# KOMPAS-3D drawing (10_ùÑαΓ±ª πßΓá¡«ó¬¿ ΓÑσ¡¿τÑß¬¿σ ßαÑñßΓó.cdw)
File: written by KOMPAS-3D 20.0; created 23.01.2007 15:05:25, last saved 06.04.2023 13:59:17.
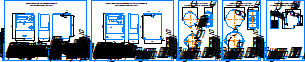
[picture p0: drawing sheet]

Sheets 1-2: A3, landscape
Sheets 3-5: A4, portrait

Document properties: Автор: Семёнов; Организация: СиТ; Разработал: Антошин; Проверил: Тарасов; Утвердил: Шмончев; Н. контр.: Силаков; Форматы листов документа: 3xA4, 2xA3; Полное имя файла: \\s-tech\depts\Отдел_ПКО\Проекты\Типовые проекты МКД 2023\!Типовой проект\1_Типовой проект МКД_RS-485\10_Чертёж установки технических средств.cdw

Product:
- Part/product: (unnamed)
  - Component: \\Helios\отдел_пко\Общая папка Компас\_Addons\Signatures\Signatures.lfr|Тарасов  | Полное имя файла: C:\Users\MAntoshin\AppData\Local\Temp\qlkzkl.frw; source file: C:\Program Files\ASCON\KOMPAS-3D V13\Libs\_Addons\Signatures\Signatures.lfr
  - Component: \\Helios\отдел_пко\Общая папка Компас\_Addons\Signatures\Signatures.lfr|Силаков  | Полное имя файла: C:\Users\MAntoshin\AppData\Local\Temp\eiczbt.frw; source file: C:\Program Files\ASCON\KOMPAS-3D V13\Libs\_Addons\Signatures\Signatures.lfr
  - Component: \\Helios\отдел_пко\Общая папка Компас\_Addons\Signatures\Signatures.lfr|Шмончев  | Полное имя файла: C:\Users\MAntoshin\AppData\Local\Temp\hsklda.frw; source file: C:\Program Files\ASCON\KOMPAS-3D V13\Libs\_Addons\Signatures\Signatures.lfr

Title block, sheet 1: designation: ВЛСТ 1277.01.000 СА; sheet number: 1; Количество листов документа: 30; organisation: АО ГК "Системы и Технологии"; Форматы листов документа: A3; stored path: \\Helios\departments\Отдел_ПКО\Проекты\Бийский Олеумный Завод\Проект\2_Рабочая документация\1_ГПП-2\СА_001_01_Чертёж установки технических средств.cdw; cell 302: Система учета электроэнергии (с организацией удаленного сбора данных) / потребителей; cell 303: Типовой проект АСКУЭ многоквартирного / дома с использованием проводного / канала связи RS-485; cell 304: Чертеж установки / технических средств; cell 320: Р
Title block, sheet 2: sheet number: 2; sheet number: 7; Форматы листов документа: A4; stored path: \\s-tech\depts\Отдел_ПКО\Проекты\Типовые проекты МКД 2023\!Типовой проект\1_Типовой проект МКД_RS-485\_Чертёж установки технических средств.cdw
Title block, sheet 3: sheet number: 3
Title block, sheet 4: sheet number: 4; stored path: \\Helios\отдел_пко\Проекты\МРСК Северо-Запада Псковэнерго\Проект\02-07_Рабочая документация\04_Многоквартирный дом,Г.Псков, ул. Юбилейная д.42\СА_001_Чертёж установки технических средств.cdw
Title block, sheet 5: sheet number: 5; sheet number: 8; stored path: \\Helios\Отдел_ПКО\Проекты\МРСК Северо-Запада Псковэнерго\Типовой проект\СА_001_Чертёж установки технических средств.cdw; designation, second copy: ВЛСТ 1277.01.000 СА-

Referenced files in \\Helios\отдел_пко\Общая папка Компас\_Addons\Signatures\: Signatures.lfr|Тарасов, Signatures.lfr, Signatures.lfr|Силаков, Signatures.lfr|Шмончев
Referenced files in C:\Program Files\ASCON\KOMPAS-3D V13\Libs\_Addons\Signatures\: Signatures.lfr
Referenced files: qlkzkl.frw, eiczbt.frw, hsklda.frw
Referenced files in C:\Program Files\ASCON\KOMPAS-3D v20\Sys\: Lighting.lts
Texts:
  Тарасов
  Силаков
  Шмончев
  Normal
  Термин
  Список определений
  Адреса
  Цитаты
  Готовый
  Courier New
  z-Bottom of Form
  z-Top of Form
  Лит-Масса-Масштаб
  Материал-Предприятие
  Z-начало формы
  Z-конец формы
  Форматированный
  Адрес
  Обычный
  heading 2
  Body Text
  heading 1
  Без имени
  txt
  footer
  heading 8
  Centerline
  Outline
  Счетчик электрической энергии однофазный КВАНТ ST1000-9
  Присоединительные и установочные размеры
  Разветвительная коробка RS-485
  Габаритные, присоединительные и установочные размеры
  Проволока
  Пломба
  1. Размеры для справок.
  2. При монтаже оборудования необходимо использовать специализированные наборы для
  крепления оборудования.
  3. При установке счетчика  КВАНТ ST1000-9 необходимо руководствоваться правилами «ПУЭ»
  (седьмое издание, глава 1.5) и руководством по эксплутации счетчика  КВАНТ ST1000-9
  ВЛСТ.418.00.000 РЭ.
  4. Пломбирование счетчика  КВАНТ ST1000-9 производить скрученной проволокой пломбировочной и свинцовой пломбой
  диаметром 10мм. Либо самоклеющейся номерной разрушаемой пломбой.
  Активная разветвительная коробка RS-485
  Автоматический выключатель BA 47-29 2Р 6А
  Счетчик электрической энергии трехфазный прямого включения КВАНТ ST2000-12
  1. При монтаже оборудования необходимо использовать специализированные наборы для
  2. При установке счетчика  КВАНТ ST1000-12 необходимо руководствоваться правилами «ПУЭ»
  (седьмое издание, глава 1.5) и руководством по эксплутации счетчика  КВАНТ ST1000-12
  ВЛСТ.419.00.000 РЭ.
  3. Пломбирование счетчика  КВАНТ ST1000-12 производить скрученной проволокой пломбировочной и свинцовой пломбой
  POLYLINE_STYLE_0.25_RGB_0_0_0
  ANSI37
  Разраб.
  Антошин
  Чертёж установки
  03 Рабочие чертежи основного комплекта. ГОСТ Р 21.1101-2009 Ф3
  05 Чертежи строительных изделий. Посл. листы. ГОСТ Р 21.1101-2009 Ф6
  05 Чертежи строительных изделий. Посл. листы.  ГОСТ 21.101-97 Ф6
Dimensions and other numbers on the sheet: 35; 2; 50; 2 отв.; 4; 88; 40; 168; 75; 130; 150; 107; 6; 10; 252; 176; 93; 158; 220; 12; 5; 45; 98; 36; 74,43; 36,49; 77,46; 34,29; 1; 02.23; 30; 7; 3; 8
